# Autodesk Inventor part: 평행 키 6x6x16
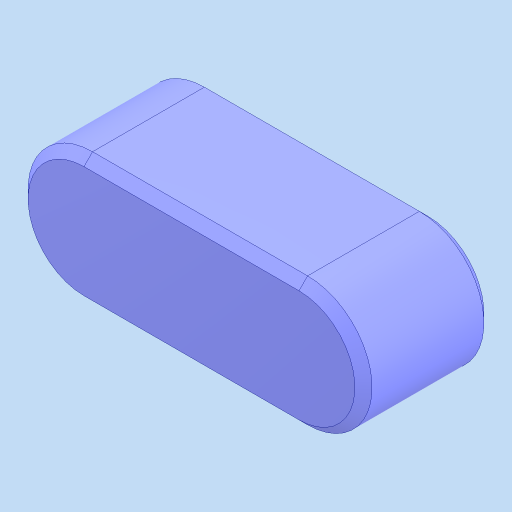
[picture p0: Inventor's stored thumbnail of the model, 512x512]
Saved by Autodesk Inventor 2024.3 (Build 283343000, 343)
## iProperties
Created: 2025-11
Part Number: 평행 키 6x6x16
Material: 강철, 연강
Description: 키 및 해당 키홈
Document SubType Name: Modeling
Designer: PC2-02
Density: 7.85 g/cm^3
Appearance: 기본값
Author: jhkim
Sending System: Autodesk Inventor 2026
Preprocessor: ST-DEVELOPER v20.1
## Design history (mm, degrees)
node "평행 키 6x6x161"
node "솔리드1"
body "Solid1"
